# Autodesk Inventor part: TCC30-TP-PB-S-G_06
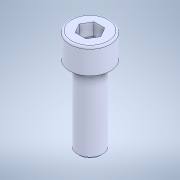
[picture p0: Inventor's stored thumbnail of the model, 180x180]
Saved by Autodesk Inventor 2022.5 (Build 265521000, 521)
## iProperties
Created: 2023-09
Part Number: TCC30-TP-PB-S-G_06
Material: 一般
Document SubType Name: Modeling
Designer: ImaoCorp
Density: 1 g/cm^3
Appearance: 既定
Author: ImaoCorp
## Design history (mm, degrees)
feature "TCC30-TP-PB-S-G_06"
node "ソリッド1"
